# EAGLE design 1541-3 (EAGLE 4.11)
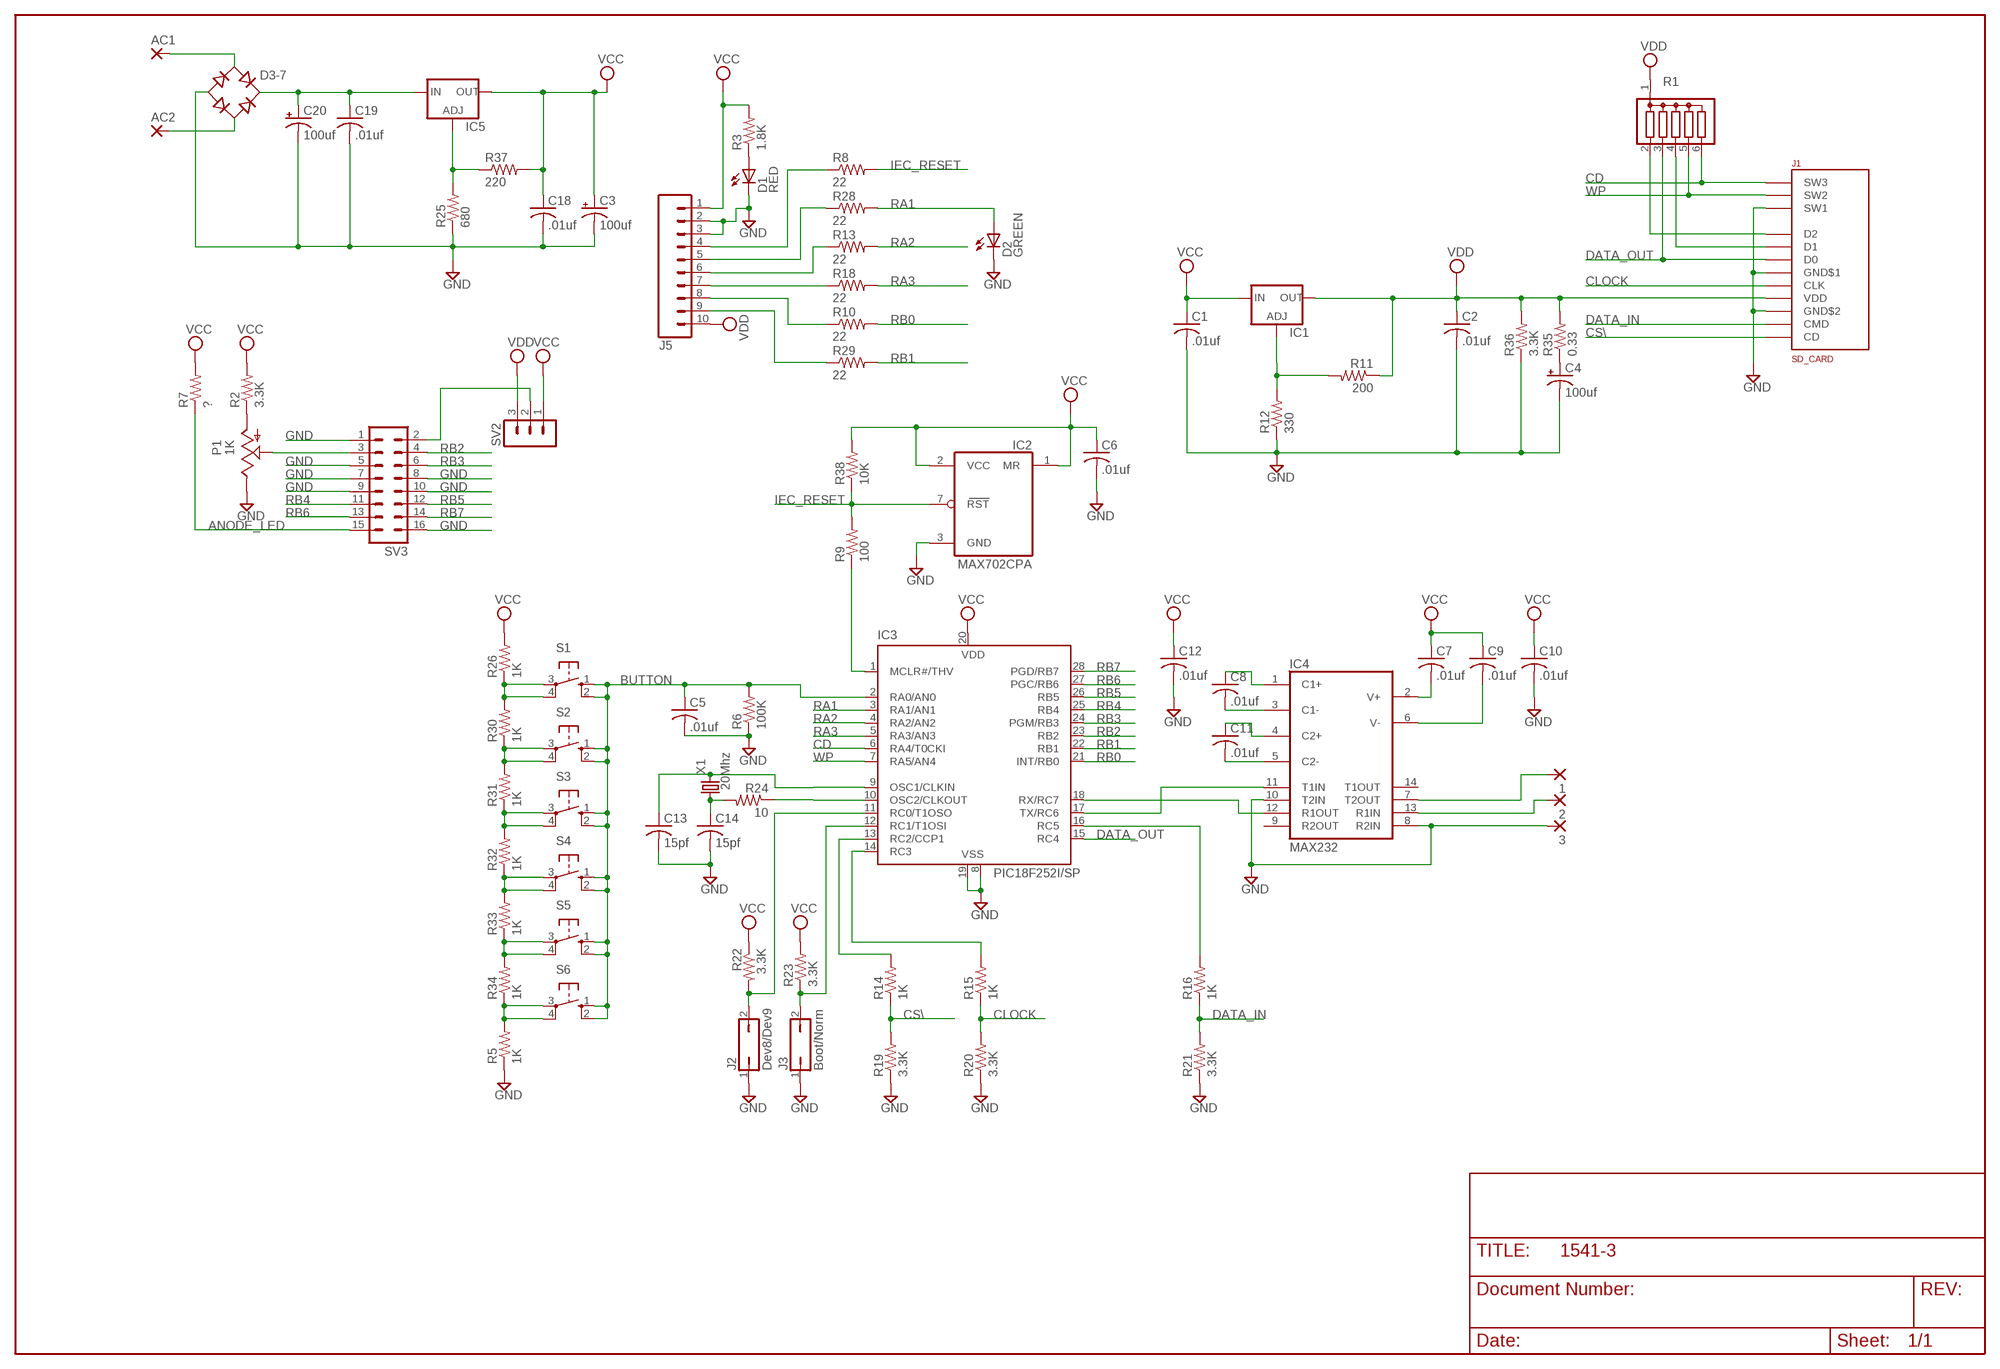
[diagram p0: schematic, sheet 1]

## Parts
1  2,15/1,0  [2,15/1,0]
2  2,15/1,0  [2,15/1,0]
3  2,15/1,0  [2,15/1,0]
AC1  2,15/1,0  [2,15/1,0]
AC2  2,15/1,0  [2,15/1,0]
C1  .01uf  C-US025-024X044  [C025-024X044]
C2  .01uf  C-US025-024X044  [C025-024X044]
C3  100uf  CPOL-USE2-5  [E2-5]
C4  100uf  CPOL-USE2-5  [E2-5]
C5  .01uf  C-US025-024X044  [C025-024X044]
C6  .01uf  C-US025-024X044  [C025-024X044]
C7  .01uf  C-US025-024X044  [C025-024X044]
C8  .01uf  C-US025-024X044  [C025-024X044]
C9  .01uf  C-US025-024X044  [C025-024X044]
C10  .01uf  C-US025-024X044  [C025-024X044]
C11  .01uf  C-US025-024X044  [C025-024X044]
C12  .01uf  C-US025-024X044  [C025-024X044]
C13  15pf  C-US025-024X044  [C025-024X044]
C14  15pf  C-US025-024X044  [C025-024X044]
C18  .01uf  C-US025-024X044  [C025-024X044]
C19  .01uf  C-US025-024X044  [C025-024X044]
C20  100uf  CPOL-USE2-5  [E2-5]
D1  RED  LED3MM  [LED3MM]
D2  GREEN  LED3MM  [LED3MM]
D3-7  RB1A  [RB1A]
IC1  LM317TS  [317TS]
IC2  MAX702CPA  [DIL08]
IC3  PIC18F252I/SP  PIC16F870P  [DIL28-3]
IC4  MAX232  [DIL16]
IC5  LM317TS  [317TS]
J1  SD_CARD  [SD_CARD]
J2  Dev8/Dev9  JP1Q  [JP1]
J3  Boot/Norm  JP1Q  [JP1]
J5  M10  [10P]
P1  1K  TRIM_US-LI10  [LI10]
R1  G05R  [SIL6]
R2  3.3K  R-US_0207/2V  [0207/2V]
R3  1.8K  R-US_0207/2V  [0207/2V]
R5  1K  R-US_0207/2V  [0207/2V]
R6  100K  R-US_0207/2V  [0207/2V]
R7  ?  R-US_0207/2V  [0207/2V]
R8  22  R-US_0207/2V  [0207/2V]
R9  100  R-US_0207/2V  [0207/2V]
R10  22  R-US_0207/2V  [0207/2V]
R11  200  R-US_0207/2V  [0207/2V]
R12  330  R-US_0207/2V  [0207/2V]
R13  22  R-US_0207/2V  [0207/2V]
R14  1K  R-US_0207/2V  [0207/2V]
R15  1K  R-US_0207/2V  [0207/2V]
R16  1K  R-US_0207/2V  [0207/2V]
R18  22  R-US_0207/2V  [0207/2V]
R19  3.3K  R-US_0207/2V  [0207/2V]
R20  3.3K  R-US_0207/2V  [0207/2V]
R21  3.3K  R-US_0207/2V  [0207/2V]
R22  3.3K  R-US_0207/2V  [0207/2V]
R23  3.3K  R-US_0207/2V  [0207/2V]
R24  10  R-US_0207/2V  [0207/2V]
R25  680  R-US_0207/2V  [0207/2V]
R26  1K  R-US_0207/2V  [0207/2V]
R28  22  R-US_0207/2V  [0207/2V]
R29  22  R-US_0207/2V  [0207/2V]
R30  1K  R-US_0207/2V  [0207/2V]
R31  1K  R-US_0207/2V  [0207/2V]
R32  1K  R-US_0207/2V  [0207/2V]
R33  1K  R-US_0207/2V  [0207/2V]
R34  1K  R-US_0207/2V  [0207/2V]
R35  0.33  R-US_0207/2V  [0207/2V]
R36  3.3K  R-US_0207/2V  [0207/2V]
R37  220  R-US_0207/2V  [0207/2V]
R38  10K  R-US_0207/2V  [0207/2V]
S1  10-XX  [B3F-10XX]
S2  10-XX  [B3F-10XX]
S3  10-XX  [B3F-10XX]
S4  10-XX  [B3F-10XX]
S5  10-XX  [B3F-10XX]
S6  10-XX  [B3F-10XX]
SV2  MA03-1  [MA03-1]
SV3  ML16  [ML16]
X1  20Mhz  CRYTALHC49U70  [HC49U70]

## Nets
ANODE_LED: R7.1 SV3.15
BUTTON: C5.1 IC3.2(RA0/AN0) R6.2 S1.1(S) S1.2(S1) S2.1(S) S2.2(S1) S3.1(S) S3.2(S1) S4.1(S) S4.2(S1) S5.1(S) S5.2(S1) S6.1(S) S6.2(S1)
CD: IC3.6(RA4/T0CKI) J1.SW3 R1.6
CLOCK: J1.CLK R15.1 R20.2
CS\: J1.DAT3(CD) R14.1 R19.2
DATA_IN: J1.CMD R16.1 R21.2
DATA_OUT: IC3.15(RC4) J1.DAT0(D0) R1.3
GND: 3.1(P) C1.2 C2.2 C3.- C4.- C5.2 C6.2 C10.2 C12.2 C13.2 C14.2 C18.2 C19.2 C20.- D1.K(C) D2.K(C) D3-7.- IC2.3(GND) IC3.8(VSS) IC3.19(VSS) IC4.8(R2IN) IC4.10(T2IN) J1.SW1 J1.VSS$1(GND$1) J1.VSS$2(GND$2) J2.1 J3.1 J5.2 J5.3 P1.E R5.1 R6.1 R12.1 R19.1 R20.1 R21.1 R25.1 R36.1 SV3.1 SV3.5 SV3.7 SV3.8 SV3.9 SV3.10 SV3.16
IEC_RESET: IC2.7(RST) R8.2 R9.2 R38.1
N$1: C4.+ R35.1
N$2: J1.DAT2(D2) R1.2
N$3: J1.DAT1(D1) R1.4
N$4: J5.9 R29.1
N$5: J5.8 R10.1
N$6: J5.7 R18.1
N$7: J5.4 R8.1
N$8: J5.5 R28.1
N$9: J5.6 R13.1
N$10: D1.A R3.1
N$11: IC3.18(RX/RC7) IC4.12(R1OUT)
N$12: IC3.14(RC3) R15.2
N$13: C14.1 R24.2 X1.1
N$14: IC3.1(MCLR#/THV) R9.1
N$15: C11.1 IC4.4(C2+)
N$16: C11.2 IC4.5(C2-)
N$17: C8.2 IC4.3(C1-)
N$18: C8.1 IC4.1(C1+)
N$19: C7.2 IC4.2(V+)
N$20: C13.1 IC3.9(OSC1/CLKIN) X1.2
N$21: IC3.10(OSC2/CLKOUT) R24.1
N$22: IC3.12(RC1/T1OSI) J3.2 R23.1
N$23: IC3.11(RC0/T1OSO) J2.2 R22.2
N$24: IC3.13(RC2/CCP1) R14.2
N$25: IC3.16(RC5) R16.2
N$26: IC1.1(ADJ) R11.2 R12.2
N$27: IC3.17(TX/RC6) IC4.11(T1IN)
N$28: R26.1 R30.2 S1.3(P) S1.4(P1)
N$29: R30.1 R31.2 S2.3(P) S2.4(P1)
N$30: R31.1 R32.2 S3.3(P) S3.4(P1)
N$31: R5.2 R34.1 S6.3(P) S6.4(P1)
N$32: R33.1 R34.2 S5.3(P) S5.4(P1)
N$33: R32.1 R33.2 S4.3(P) S4.4(P1)
N$34: P1.A R2.1
N$35: SV2.2 SV3.2
N$36: P1.S SV3.3
N$37: C9.2 IC4.6(V-)
N$38: IC5.1(ADJ) R25.2 R37.1
N$39: AC1.1(P) D3-7.AC1
N$40: C19.1 C20.+ D3-7.+ IC5.3(IN)
N$41: AC2.1(P) D3-7.AC2
N$42: 2.1(P) IC4.13(R1IN)
N$43: 1.1(P) IC4.7(T2OUT)
RA1: D2.A IC3.3(RA1/AN1) R28.2
RA2: IC3.4(RA2/AN2) R13.2
RA3: IC3.5(RA3/AN3) R18.2
RB0: IC3.21(INT/RB0) R10.2
RB1: IC3.22(RB1) R29.2
RB2: IC3.23(RB2) SV3.4
RB3: IC3.24(PGM/RB3) SV3.6
RB4: IC3.25(RB4) SV3.11
RB5: IC3.26(RB5) SV3.12
RB6: IC3.27(PGC/RB6) SV3.13
RB7: IC3.28(PGD/RB7) SV3.14
VCC: C1.1 C3.+ C6.1 C7.1 C9.1 C10.1 C12.1 C18.1 IC1.3(IN) IC2.1(MR) IC2.2(VCC) IC3.20(VDD) IC5.2(OUT) J5.1 R2.2 R3.2 R7.2 R22.1 R23.2 R26.2 R37.2 R38.2 SV2.1
VDD: C2.1 IC1.2(OUT) J1.VDD J5.10 R1.1 R11.1 R35.2 R36.2 SV2.3
WP: IC3.7(RA5/AN4) J1.SW2 R1.5
Unconnected: IC4.9(R2OUT) IC4.14(T1OUT)

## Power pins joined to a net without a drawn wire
GND: IC4.15(GND)
VCC: IC4.16(VCC)

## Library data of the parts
1-3 AC1 AC2 = wirepad:2,15/1,0: THROUGH-HOLE PAD
C1 C2 C5-C14 C18 C19 = rcl:C-US: CAPACITOR, American symbol
C3 C4 C20 = rcl:CPOL-US: POLARIZED CAPACITOR, American symbol
D1 D2 = led:LED: LED
D3-7 = rectifier:RB1A: RECTIFIER 1 A
IC1 IC5 = v-reg:LM317TS: VOLTAGE REGULATOR
IC2 = maxim:MAX702CPA: POWER SUPPLY MONITOR
IC3 = microchip:PIC16*870: MICROCONTROLLER flash type
IC4 = maxim:MAX232: RS232 TRANSEIVER
J1 = 1541-III:SD_CARD: SD Card Socket
J2 J3 = jumper:JP1Q: JUMPER
J5 = con-amp-quick:M10: AMP QUICK CONNECTOR
P1 = pot:TRIM_US-: POTENTIOMETER
R1 = resistor-sil:G05R: SIL RESISTOR
R2 R3 R5-R16 R18-R26 R28-R38 = rcl:R-US_: RESISTOR, American symbol
S1-S6 = switch-omron:10-XX: OMRON SWITCH
SV2 = con-lstb:MA03-1: PIN HEADER
SV3 = con-harting-ml:ML16: HARTING
X1 = crystal:CRYTAL: CRYSTAL

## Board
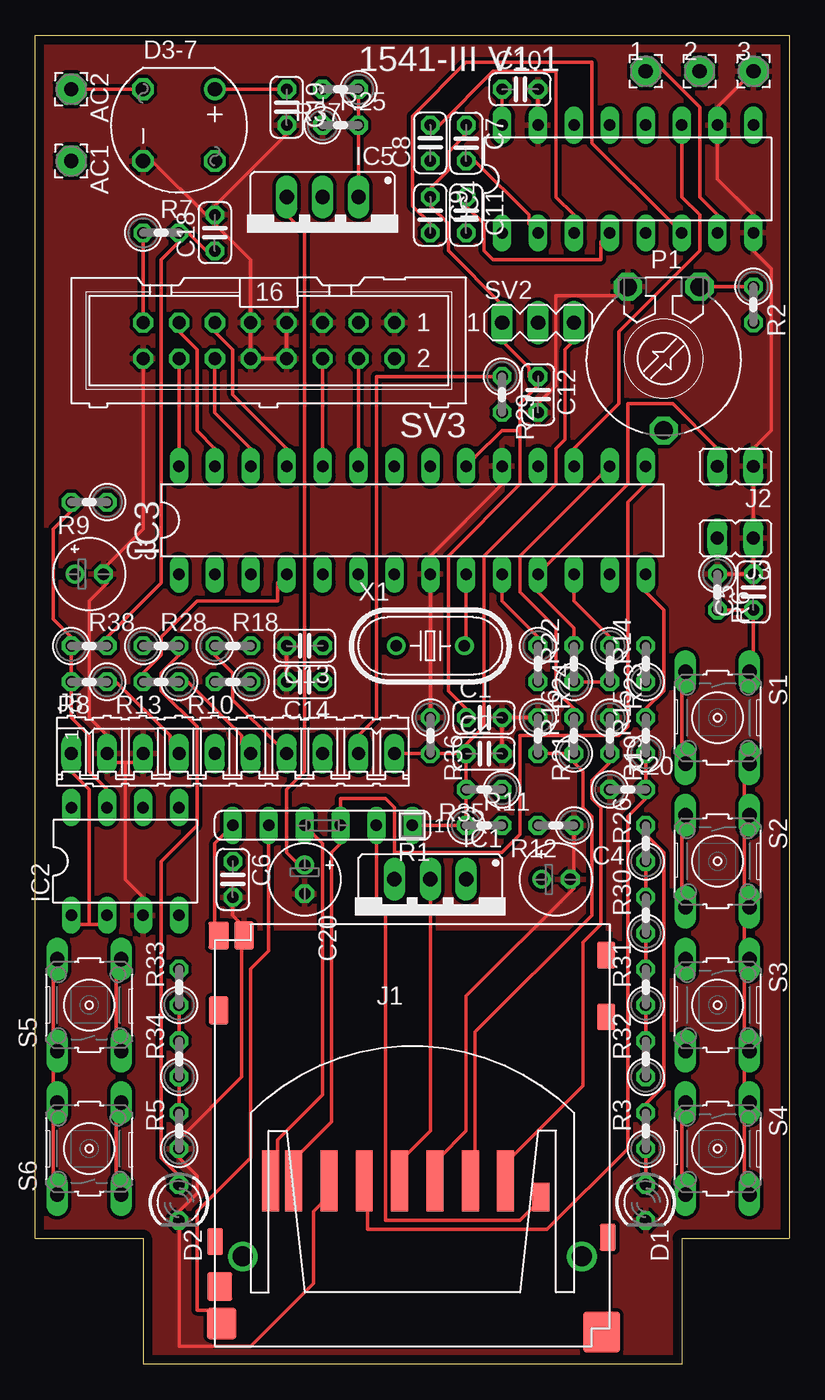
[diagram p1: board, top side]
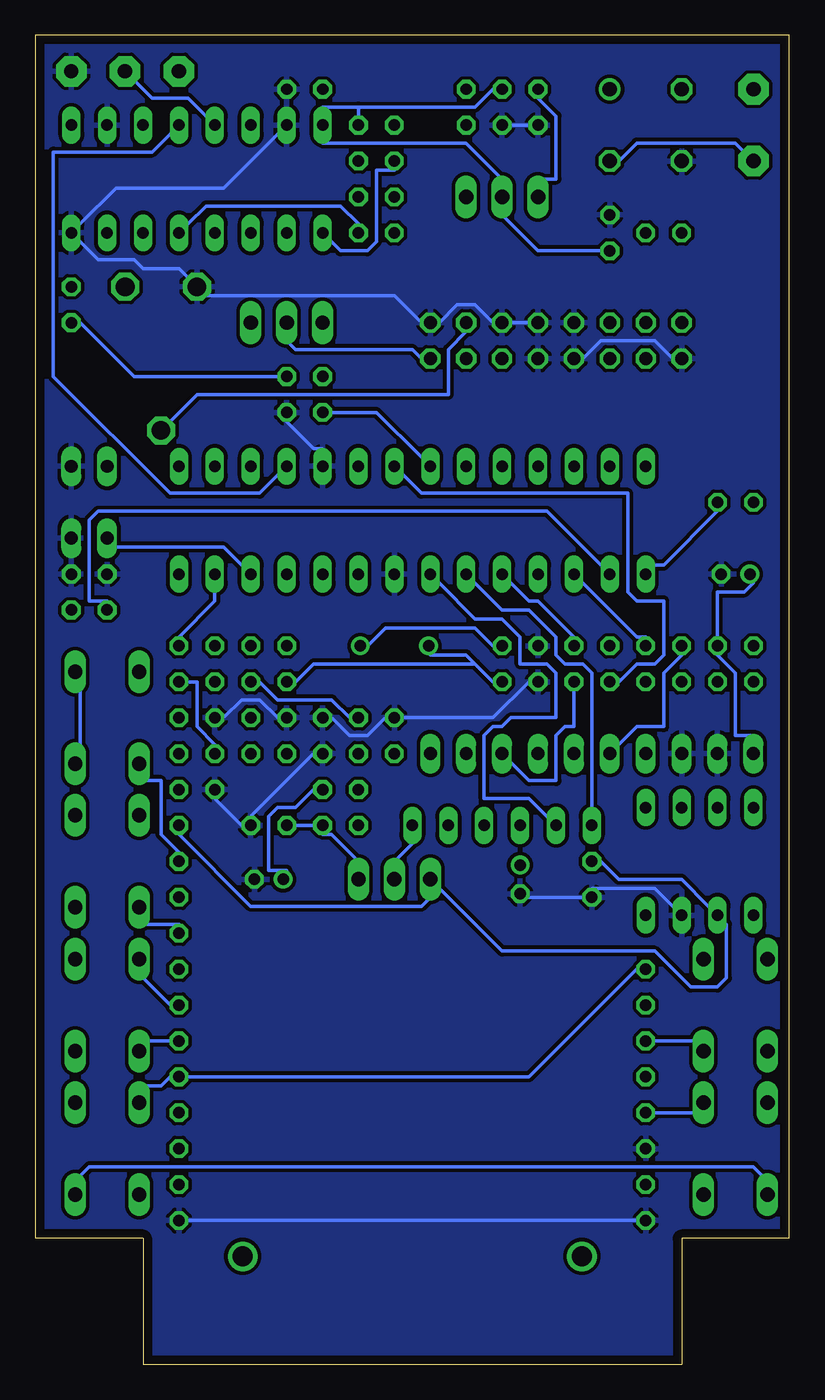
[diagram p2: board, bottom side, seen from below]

Size 53.34 x 93.98 mm. Coordinates in mm from the lower left corner, seen from the top.
Outline: 0,93.98 53.34,93.98 53.34,8.89 45.72,8.89 45.72,0 7.62,0 7.62,8.89 0,8.89 0,93.98
Copper layers (1*16): Top 0.035mm / dielectric 1.5mm / Bottom 0.035mm
Design rules "olimex10mil": minimum track width 10mil, minimum drill 24mil, track to track 10mil, track to pad 10mil, pad to pad 10mil, via to via 10mil, smd to smd 10mil, copper to edge 25mil, drill to drill 10mil, minimum pad ring 10mil, minimum via ring 8mil, stop-mask expansion 0mil, vias tented up to drill 0mil, thermal gap 10mil
tRestrict: area 12.7,1.3 to 40.6,30.5

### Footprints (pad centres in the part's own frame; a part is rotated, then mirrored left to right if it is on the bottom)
2,15/1,0 = drill 1.016 pad 2.159 octagon: 1 0,0
C025-024X044 = drill 0.813 octagon: 1 -1.27,0; 2 1.27,0
E2-5 = drill 0.813 pad 1.27 round: + -1.016,0 | drill 0.813 pad 1.27 octagon: - 1.016,0
LED3MM = drill 0.813 octagon: A -1.27,0; K 1.27,0
RB1A = drill 1.016 round: + -2.54,2.54 | drill 1.016 octagon: - 2.54,-2.54; AC1 2.54,2.54; AC2 -2.54,-2.54
317TS = drill 1.016 long: 1 -2.54,-2.54; 2 0,-2.54; 3 2.54,-2.54
DIL08 = drill 0.813 long: 1 -3.81,-3.81; 2 -1.27,-3.81; 3 1.27,-3.81; 4 3.81,-3.81; 5 3.81,3.81; 6 1.27,3.81; 7 -1.27,3.81; 8 -3.81,3.81
DIL28-3 = drill 0.813 long: 1 -16.51,-3.81; 2 -13.97,-3.81; 3 -11.43,-3.81; 4 -8.89,-3.81; 5 -6.35,-3.81; 6 -3.81,-3.81; 7 -1.27,-3.81; 8 1.27,-3.81; 9 3.81,-3.81; 10 6.35,-3.81; 11 8.89,-3.81; 12 11.43,-3.81; 13 13.97,-3.81; 14 16.51,-3.81; 15 16.51,3.81; 16 13.97,3.81; 17 11.43,3.81; 18 8.89,3.81; 19 6.35,3.81; 20 3.81,3.81; 21 1.27,3.81; 22 -1.27,3.81; 23 -3.81,3.81; 24 -6.35,3.81; 25 -8.89,3.81; 26 -11.43,3.81; 27 -13.97,3.81; 28 -16.51,3.81
DIL16 = drill 0.813 long: 1 -8.89,-3.81; 2 -6.35,-3.81; 3 -3.81,-3.81; 4 -1.27,-3.81; 5 1.27,-3.81; 6 3.81,-3.81; 7 6.35,-3.81; 8 8.89,-3.81; 9 8.89,3.81; 10 6.35,3.81; 11 3.81,3.81; 12 1.27,3.81; 13 -1.27,3.81; 14 -3.81,3.81; 15 -6.35,3.81; 16 -8.89,3.81
SD_CARD = smd 1.2 x 4.3: CLK -3.4,5.34; CMD 4.1,5.34; DAT0 -8.4,5.34; DAT1 -10.025,5.34; DAT3 6.6,5.34; VDD -0.9,5.34; VSS$1 1.6,5.34; VSS$2 -5.9,5.34 | smd 1.2 x 2: DAT2 9.1,4.19 | smd 1.4 x 1.95: GND$1 -13.7,17.4; SW1 -11.9,22.7 | smd 1.143 x 1.905: GND$2 -13.954,1.05; GND$6 13.827,1.35 | smd 1.778 x 2.032: GND$3 -13.627,-2.127 | smd 1.3 x 1.9: GND$4 13.7,21.3; GND$5 13.7,16.95 | smd 2.6 x 2.9: GND$7 13.4,-5.35 | drill 1.4 pad 1.5 round: GND$8 -12,0; GND$9 12,0 | smd 2.1 x 2.2: SW2 -13.5,-4.75 | smd 1.45 x 1.95: SW3 -13.7,22.7
JP1 = drill 0.914 long: 1 0,-1.27; 2 0,1.27
10P = drill 0.914 long: 1 -11.43,0; 2 -8.89,0; 3 -6.35,0; 4 -3.81,0; 5 -1.27,0; 6 1.27,0; 7 3.81,0; 8 6.35,0; 9 8.89,0; 10 11.43,0
LI10 = drill 1.321 octagon: A -2.54,-5.08; E 2.54,-5.08; S 0,5.08
SIL6 = drill 0.813 long: 1 -6.35,0; 2 -3.81,0; 3 -1.27,0; 4 1.27,0; 5 3.81,0; 6 6.35,0
0207/2V = drill 0.813 octagon: 1 -1.27,0; 2 1.27,0
B3F-10XX = drill 1.016 long: 1 -3.251,2.261; 2 3.251,2.261; 3 -3.251,-2.261; 4 3.251,-2.261
MA03-1 = drill 1.016 long: 1 -2.54,0; 2 0,0; 3 2.54,0
ML16 = drill 0.914 octagon: 1 -8.89,-1.27; 2 -8.89,1.27; 3 -6.35,-1.27; 4 -6.35,1.27; 5 -3.81,-1.27; 6 -3.81,1.27; 7 -1.27,-1.27; 8 -1.27,1.27; 9 1.27,-1.27; 10 1.27,1.27; 11 3.81,-1.27; 12 3.81,1.27; 13 6.35,-1.27; 14 6.35,1.27; 15 8.89,-1.27; 16 8.89,1.27
HC49U70 = drill 0.813 round: 1 -2.413,0; 2 2.413,0

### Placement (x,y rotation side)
1  43.18,91.44 0 top
2  46.99,91.44 0 top
3  50.8,91.44 0 top
AC1  2.54,85.09 270 top
AC2  2.54,90.17 270 top
C1  31.75,45.72 0 top
C2  31.75,43.18 0 top
C3  3.81,55.88 0 top
C4  36.83,34.29 0 top
C5  50.8,54.61 90 top
C6  13.97,34.29 270 top
C7  30.48,86.36 270 top
C8  27.94,86.36 90 top
C9  27.94,81.28 270 top
C10  34.29,90.17 0 top
C11  30.48,81.28 270 top
C12  35.56,68.58 270 top
C13  19.05,50.8 180 top
C14  19.05,48.26 180 top
C18  12.7,80.01 90 top
C19  17.78,88.9 270 top
C20  19.05,34.29 270 top
D1  43.18,11.43 270 top
D2  10.16,11.43 270 top
D3-7  10.16,87.63 270 top
IC1  27.94,31.75 180 top
IC2  6.35,35.56 0 top
IC3  26.67,59.69 0 top
IC4  41.91,83.82 0 top
IC5  20.32,80.01 180 top
J1  26.67,7.62 0 top
J2  49.53,63.5 90 top
J3  49.53,58.42 90 top
J5  13.97,43.18 0 top
P1  44.45,71.12 180 top
R1  20.32,38.1 180 top
R2  50.8,74.93 270 top
R3  43.18,16.51 90 top
R5  10.16,16.51 90 top
R6  48.26,54.61 270 top
R7  8.89,80.01 0 top
R8  3.81,48.26 180 top
R9  3.81,60.96 180 top
R10  13.97,48.26 180 top
R11  31.75,38.1 0 top
R12  36.83,38.1 180 top
R13  8.89,48.26 180 top
R14  43.18,49.53 90 top
R15  43.18,44.45 90 top
R16  38.1,44.45 90 top
R18  13.97,50.8 0 top
R19  40.64,44.45 270 top
R20  41.91,40.64 0 top
R21  35.56,44.45 270 top
R22  38.1,49.53 90 top
R23  40.64,49.53 270 top
R24  35.56,49.53 270 top
R25  21.59,87.63 0 top
R26  43.18,36.83 90 top
R28  8.89,50.8 0 top
R29  33.02,68.58 270 top
R30  43.18,31.75 90 top
R31  43.18,26.67 90 top
R32  43.18,21.59 90 top
R33  10.16,26.67 90 top
R34  10.16,21.59 90 top
R35  31.75,40.64 180 top
R36  27.94,44.45 270 top
R37  21.59,90.17 180 top
R38  3.81,50.8 0 top
S1  48.26,45.72 270 top
S2  48.26,35.56 270 top
S3  48.26,25.4 270 top
S4  48.26,15.24 270 top
S5  3.81,25.4 90 top
S6  3.81,15.24 90 top
SV2  35.56,73.66 0 top
SV3  16.51,72.39 180 top
X1  27.94,50.8 0 top

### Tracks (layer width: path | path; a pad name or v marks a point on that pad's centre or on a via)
ANODE_LED
  Top 0.254: R7.1 7.62,79.38 7.62,74.3 SV3.15
BUTTON
  Top 0.254: R6.2 48.9,53.34 50.16,53.34 C5.1 50.8,52.7 50.8,50.16 S1.1 | S6.1 1.27,13.34 1.27,17.14 S6.2 1.27,19.68 1.27,20.95 S5.1 1.27,23.5 1.27,27.3 S5.2 | S1.2 50.16,41.27 50.16,40.01 S2.1 50.16,37.47 50.16,33.66 S2.2 50.16,31.11 50.16,29.84 S3.1 50.16,27.3 50.16,23.5 S3.2 50.16,20.95 50.16,19.68 S4.1 50.16,17.14 50.16,13.34 S4.2
  Bottom 0.254: IC3.2 13.34,56.52 17.14,60.33 48.9,60.33 49.53,59.69 49.53,53.98 48.26,53.98 R6.2 | S6.1 1.91,13.34 2.54,13.97 49.53,13.97 50.16,13.34 S4.2 | S1.1 50.16,47.62 50.16,43.81 S1.2
CD
  Top 0.254: J1.SW3 12.7,31.11 12.7,36.83 13.34,37.47 R1.6
  Bottom 0.254: IC3.6 22.23,55.24 20.32,53.34 18.41,53.34 16.51,51.44 16.51,50.16 15.88,49.53 14.61,49.53 13.97,48.9 13.97,39.37 R1.6
CLOCK
  Top 0.254: R15.1 43.18,42.55 43.18,41.27 R20.2 43.18,40.01 41.91,38.73 41.91,15.24 36.2,9.53 23.5,9.53 23.5,11.43 J1.CLK
CS\
  Top 0.254: J1.DAT3 33.66,14.61 38.73,19.68 38.73,29.84 40.01,31.11 40.01,39.37 39.37,40.01 39.37,41.27 40.64,42.55 R19.2
  Bottom 0.254: R19.2 40.64,43.81 41.91,45.09 41.91,48.26 42.55,48.26 R14.1
DATA_IN
  Top 0.254: R21.2 36.2,43.18 37.47,43.18 R16.1 38.1,42.55 38.73,41.91 38.73,39.37 39.37,38.73 39.37,31.75 31.11,23.5 31.11,14.61 J1.CMD
DATA_OUT
  Top 0.254: J1.DAT0 18.41,14.61 20.95,17.14 20.95,36.2 21.59,36.83 R1.3 21.59,39.37 21.59,40.01 24.77,40.01 25.4,39.37 25.4,36.2 33.02,36.2 34.29,37.47 34.29,44.45 41.27,44.45 41.91,45.09 41.91,60.96 43.18,62.23 IC3.15
GND
  Top 0.254: R12.1 38.1,37.47 38.1,34.92 C4.- 38.1,33.66 30.48,26.04 30.48,16.51 28.57,14.61 J1.VSS$1 | IC3.19 33.02,62.23 27.94,57.15 IC3.8 27.94,54.61 27.94,46.35 R36.1 | C14.2 17.78,48.9 17.78,50.16 C13.2 | C2.2 33.02,43.81 33.02,45.09 C1.2 33.66,45.72 34.92,45.72 R21.1 | J1.VSS$2 20.32,11.43 19.68,10.79 19.68,5.71 15.24,1.27 10.16,1.27 10.16,9.53 D2.K 10.16,10.79 11.43,12.06 11.43,13.34 10.16,14.61 R5.1 10.16,15.88 14.61,20.32 14.61,29.84 J1.SW1 14.61,31.11 13.97,31.75 13.97,32.38 C6.2 | 6.35,42.55 5.71,42.55 J5.2 5.08,44.45 3.81,45.72 3.81,53.98 5.08,55.24 C3.- 5.08,56.52 7.62,59.05 7.62,70.48 SV3.16 | 6.35,42.55 6.99,42.55 J5.3 | 6.35,42.55 6.35,34.29 7.62,33.02 IC2.3 | C18.2 12.06,81.28 8.26,85.09 D3-7.- | C19.2 17.78,87 12.7,81.92 C18.2 | SV3.7 17.78,73.03 17.78,71.75 SV3.8 17.14,71.12 15.88,71.12 SV3.10 15.24,71.75 15.24,73.03 SV3.9 15.24,74.3 15.24,78.11 12.7,80.64 C18.2 | R6.1 48.9,55.88 50.16,55.88 C5.2 50.8,56.52 50.8,57.15 J3.1 50.8,59.69 50.8,62.23 J2.1 50.8,64.77 52.07,66.04 52.07,77.47 50.8,78.74 IC4.8 50.8,81.28 48.26,83.82 48.26,86.36 IC4.10 48.26,88.9 50.16,90.81 3.1 | IC4.15 35.56,88.9 35.56,89.53 C10.2 | C12.2 35.56,67.94 36.83,69.22 36.83,75.56 41.27,75.56 P1.E
  Bottom 0.254: R20.1 40.64,40.01 38.73,38.1 R12.1 38.1,38.73 33.66,43.18 C2.2 | C12.2 35.56,66.67 33.66,64.77 33.02,64.77 IC3.19 | C1.2 32.38,45.72 31.11,44.45 29.84,44.45 28.57,45.72 R36.1 27.3,45.72 20.95,45.72 18.41,48.26 C14.2 | R19.1 40.01,45.72 38.73,46.99 37.47,46.99 36.2,45.72 R21.1 | D1.K 42.55,10.16 10.79,10.16 D2.K | IC2.3 8.26,32.38 9.53,33.66 13.97,33.66 C6.2 14.61,33.02 18.41,33.02 C20.- | C19.2 18.41,87.63 19.68,87.63 R25.1 | SV3.16 8.26,71.12 9.53,72.39 13.34,72.39 14.61,71.12 SV3.10 | SV3.7 18.41,73.66 19.68,73.66 SV3.5 20.95,73.66 22.23,74.93 23.5,74.93 24.77,73.66 SV3.1 26.04,73.66 27.94,75.56 41.27,75.56 P1.E 42.55,76.83 43.18,77.47 45.72,77.47 46.35,78.11 48.9,78.11 50.16,79.38 IC4.8 50.16,80.64 47.62,83.19 40.01,83.19 36.2,87 IC4.15
  pour Top: 53.34,0 0,0 0,93.98 53.34,93.98
  pour Bottom: 53.34,0 0,0 0,93.98 53.34,93.98
IEC_RESET
  Top 0.254: IC2.7 5.08,40.64 3.81,41.91 3.81,44.45 2.54,45.72 2.54,47.62 R8.2 2.54,48.9 2.54,50.16 R38.1 2.54,51.44 1.27,52.7 1.27,59.05 2.54,60.33 R9.2
N$1
  Bottom 0.254: R35.1 33.66,40.64 34.92,39.37 36.2,39.37 36.83,38.73 36.83,34.92 35.56,34.92 C4.+
N$2
  Top 0.254: J1.DAT2 35.56,11.43 34.29,10.16 24.77,10.16 24.77,31.75 24.13,32.38 24.13,36.83 R1.2
N$3
  Top 0.254: R1.4 19.68,37.47 20.32,36.83 20.32,19.05 17.14,15.88 17.14,14.61 J1.DAT1
N$4
  Top 0.254: R29.1 32.38,69.85 24.13,69.85 24.13,45.72 22.86,44.45 J5.9
N$5
  Bottom 0.254: R10.1 15.24,47.62 15.24,45.09 15.88,45.09 16.51,44.45 16.51,41.27 18.41,41.27 19.68,42.55 J5.8
N$6
  Top 0.254: R18.1 12.7,50.16 13.97,48.9 13.97,46.99 17.14,43.81 J5.7
N$7
  Top 0.254: R8.1 5.71,48.26 9.53,44.45 9.53,43.81 J5.4
N$8
  Bottom 0.254: R28.1 7.62,50.16 8.89,48.9 8.89,45.09 10.79,45.09 12.06,43.81 J5.5
N$9
  Top 0.254: R13.1 10.79,48.26 14.61,44.45 14.61,43.81 J5.6
N$10
  Top 0.254: D1.A 43.18,13.34 43.18,14.61 R3.1
N$11
  Bottom 0.254: IC3.18 36.2,62.87 37.47,61.59 43.81,61.59 52.07,69.85 52.07,85.72 45.09,85.72 43.81,87 IC4.12
N$12
  Top 0.254: R15.2 43.18,46.35 44.45,47.62 44.45,53.34 43.18,54.61 IC3.14
N$13
  Bottom 0.254: 22.23,49.53 22.86,50.16 25.4,50.16 X1.1 | 22.23,49.53 20.95,48.26 C14.1 | 22.23,49.53 33.66,49.53 34.92,48.26 R24.2
N$14
  Bottom 0.254: R9.1 5.08,60.33 8.89,56.52 9.53,56.52 IC3.1
N$15
  Top 0.254: C11.1 30.48,81.92 31.75,80.64 31.75,78.74 32.38,78.11 40.01,78.11 40.01,79.38 IC4.4
N$16
  Bottom 0.254: C11.2 30.48,80.64 31.75,81.92 41.27,81.92 42.55,80.64 IC4.5
N$17
  Top 0.254: C8.2 28.57,87.63 32.38,91.44 36.83,91.44 36.83,82.55 38.1,81.28 IC4.3
N$18
  Bottom 0.254: IC4.1 32.38,79.38 31.75,78.74 29.84,78.74 29.21,79.38 29.21,84.45 27.94,84.45 C8.1
N$19
  Top 0.254: C7.2 31.11,85.09 34.92,81.28 34.92,80.64 IC4.2
N$20
  Top 0.254: IC3.9 30.48,54.61 30.48,51.44 X1.2
  Bottom 0.254: C13.1 20.95,50.8 22.23,52.07 28.57,52.07 29.84,50.8 X1.2
N$21
  Top 0.254: R24.1 35.56,51.44 33.02,53.98 33.02,54.61 IC3.10
N$22
  Top 0.254: R23.1 40.64,51.44 38.1,53.98 38.1,54.61 IC3.12
  Bottom 0.254: J3.2 47.62,57.78 40.01,57.78 38.73,56.52 IC3.12
N$23
  Top 0.254: R22.2 38.1,51.44 38.1,52.07 35.56,54.61 IC3.11 36.2,56.52 41.91,62.23 41.91,67.94 45.09,67.94 48.26,64.77 J2.2
N$24
  Bottom 0.254: R14.2 43.18,51.44 40.64,53.98 40.64,54.61 IC3.13
N$25
  Top 0.254: R16.2 38.1,46.35 36.83,47.62 36.83,52.07 34.29,54.61 34.29,57.15 40.01,62.87 IC3.16
N$26
  Bottom 0.254: R12.2 34.92,38.1 33.66,38.1 R11.2 33.02,37.47 32.38,37.47 30.48,35.56 IC1.1
N$27
  Top 0.254: IC3.17 38.1,64.77 41.27,67.94 41.27,73.03 46.99,78.74 46.99,81.28 45.72,82.55 45.72,86.36 IC4.11
N$28
  Top 0.254: R30.2 43.18,33.66 43.18,34.92 R26.1 | S1.4 45.72,43.81 45.72,47.62 S1.3
  Bottom 0.254: R26.1 43.18,36.2 44.45,37.47 44.45,41.27 45.72,41.27 S1.4
N$29
  Top 0.254: R31.2 43.18,28.57 43.18,29.84 R30.1 | S2.3 45.72,37.47 45.72,33.66 S2.4
  Bottom 0.254: S2.4 45.72,31.11 43.18,31.11 R30.1
N$30
  Top 0.254: R32.2 43.18,23.5 43.18,24.77 R31.1
  Bottom 0.254: S3.4 45.72,22.86 43.81,22.86 R32.2 | S3.3 45.72,27.3 43.81,25.4 R31.1
N$31
  Top 0.254: R5.2 10.16,18.41 10.16,19.68 R34.1 | S6.3 5.71,13.34 5.71,17.14 S6.4
  Bottom 0.254: R5.2 9.53,17.78 6.35,17.78 S6.4
N$32
  Top 0.254: R34.2 10.16,23.5 10.16,24.77 R33.1 | S5.4 5.71,27.3 5.71,23.5 S5.3
  Bottom 0.254: S5.3 6.35,22.86 9.53,22.86 R34.2
N$33
  Top 0.254: S4.4 45.72,13.34 45.72,17.14 S4.3
  Bottom 0.254: S4.3 45.72,19.68 44.45,19.68 43.81,20.32 R32.1 42.55,20.32 18.41,20.32 10.79,27.94 R33.2
N$34
  Top 0.254: R2.1 50.16,76.2 47.62,76.2 P1.A
N$35
  Bottom 0.254: SV3.2 26.04,71.12 26.67,71.75 34.92,71.75 35.56,72.39 SV2.2
N$36
  Bottom 0.254: SV3.3 22.86,73.03 24.13,71.75 24.13,68.58 41.91,68.58 43.81,66.67 P1.S
N$37
  Top 0.254: C9.2 27.94,80.64 26.67,81.92 26.67,88.27 30.48,92.08 39.37,92.08 39.37,86.36 45.09,80.64 IC4.6
N$38
  Top 0.254: R37.1 22.86,89.53 22.86,88.27 R25.2 22.86,87 22.86,83.82 IC5.1
N$39
  Bottom 0.254: D3-7.AC1 12.06,85.09 10.79,86.36 3.81,86.36 3.17,85.72 AC1.1
N$40
  Top 0.254: C19.1 17.14,90.17 13.34,90.17 D3-7.+ | C20.+ 18.41,35.56 17.78,36.2 17.78,40.64 19.05,41.91 19.05,80.01 17.78,81.28 IC5.3
  Bottom 0.254: C19.1 17.78,89.53 16.51,88.27 16.51,83.82 17.78,83.82 IC5.3
N$41
  Top 0.254: D3-7.AC2 6.99,90.17 3.17,90.17 AC2.1
N$42
  Bottom 0.254: IC4.13 41.27,88.27 42.55,89.53 45.09,89.53 46.35,90.81 2.1
N$43
  Top 0.254: IC4.7 48.26,81.28 46.99,82.55 46.99,88.9 43.81,92.08 1.1
RA1
  Top 0.254: D2.A 10.16,13.34 8.89,14.61 8.89,35.56 11.43,38.1 11.43,45.09 8.89,47.62 8.89,48.9 10.16,50.16 R28.2
  Bottom 0.254: IC3.3 14.61,55.24 10.79,51.44 10.16,51.44 R28.2
RA2
  Top 0.254: R13.2 7.62,48.9 8.89,50.16 8.89,51.44 11.43,53.98 17.14,53.98 17.14,55.24 IC3.4
RA3
  Bottom 0.254: R18.2 15.24,51.44 17.78,53.98 18.41,53.98 19.68,55.24 IC3.5
RB0
  Bottom 0.254: R10.2 12.06,48.26 10.79,49.53 9.53,49.53 8.89,50.16 8.89,53.98 10.79,53.98 11.43,54.61 11.43,61.59 26.04,61.59 27.3,62.87 IC3.21
RB1
  Bottom 0.254: IC3.22 26.04,64.14 29.21,67.31 32.38,67.31 R29.2
RB2
  Top 0.254: IC3.23 22.86,64.77 22.86,70.48 SV3.4
RB3
  Top 0.254: IC3.24 20.32,64.77 20.32,70.48 SV3.6
RB4
  Top 0.254: IC3.25 17.78,64.77 13.97,68.58 13.97,71.75 12.7,73.03 SV3.11
RB5
  Top 0.254: IC3.26 15.24,64.77 12.7,67.31 12.7,70.48 SV3.12
RB6
  Top 0.254: IC3.27 12.7,64.77 11.43,66.04 11.43,71.75 10.16,73.03 SV3.13
RB7
  Top 0.254: IC3.28 10.16,64.77 10.16,70.48 SV3.14
VCC
  Top 0.254: R3.2 43.18,18.41 44.45,19.68 44.45,36.2 43.18,37.47 R26.2 | 3.81,31.11 4.45,31.11 IC2.2 | 3.81,31.11 3.17,31.11 IC2.1 | 3.81,31.11 3.81,40.64 2.54,41.91 J5.1 | C18.1 12.06,78.74 10.79,80.01 R7.2 10.16,79.38 8.89,78.11 8.89,55.24 5.08,51.44 R38.2 | C7.1 30.48,87 29.21,85.72 29.21,84.45 27.94,83.19 C9.1 27.94,81.92 29.21,80.64 29.21,78.74 33.02,74.93 SV2.1 33.02,72.39 34.92,70.48 34.92,69.85 C12.1 35.56,69.22 34.29,67.94 34.29,66.04 | C10.1 33.02,89.53 33.02,88.9 IC4.16 | R23.2 40.01,48.26 38.73,48.26 R22.1 | 34.29,66.04 33.02,66.04 31.11,64.14 IC3.20 | 34.29,66.04 34.29,62.23 29.21,57.15 29.21,47.62 30.48,46.35 C1.1
  Bottom 0.254: R26.2 43.18,37.47 38.1,32.38 26.04,32.38 25.4,33.02 IC1.3 24.77,33.66 20.32,29.21 9.53,29.21 6.99,26.67 5.08,26.67 4.45,27.3 4.45,31.11 IC2.2 5.71,32.38 7.62,34.29 12.06,34.29 13.34,35.56 C6.1 | C3.+ 2.54,55.24 3.17,54.61 5.08,54.61 5.08,51.44 R38.2 5.08,50.16 3.81,48.9 3.81,44.45 2.54,44.45 J5.1 | C18.1 13.34,78.74 17.78,78.74 20.32,81.28 IC5.2 20.32,83.82 22.86,86.36 33.02,86.36 IC4.16 33.02,88.9 30.48,88.9 | 30.48,88.9 22.23,88.9 20.95,90.17 R37.2 | 30.48,88.9 30.48,88.27 C7.1 | C1.1 31.11,45.72 32.38,46.99 36.2,46.99 37.47,48.26 R22.1 | R2.2 50.16,73.66 46.35,69.85 36.2,69.85 C12.1
VDD
  Top 0.254: J1.VDD 26.04,14.61 27.94,16.51 27.94,33.02 IC1.2 | J5.10 26.04,43.18 27.3,43.18 R36.2 28.57,43.18 29.84,43.18 C2.1 | C2.1 30.48,42.55 30.48,41.27 R35.2 30.48,40.01 30.48,38.73 R11.1 29.84,38.1 27.3,38.1 R1.1 | SV2.3 38.1,72.39 37.47,71.75 37.47,65.41 36.83,64.77 36.83,62.23 31.75,57.15 31.75,45.09 30.48,43.81 C2.1
  Bottom 0.254: R1.1 26.67,36.83 27.94,35.56 IC1.2
WP
  Top 0.254: J1.SW2 12.7,3.81 11.43,3.81 11.43,10.79 15.24,14.61 15.24,27.94 16.51,29.21 16.51,36.83 R1.5
  Bottom 0.254: IC3.7 24.77,55.24 22.23,52.7 20.32,52.7 19.05,51.44 19.05,49.53 17.14,49.53 16.51,48.9 16.51,45.72 19.68,45.72 20.32,45.09 20.95,45.09 21.59,44.45 21.59,40.01 18.41,40.01 17.14,38.73 R1.5

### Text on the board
tPlace: 1541-III V1.1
